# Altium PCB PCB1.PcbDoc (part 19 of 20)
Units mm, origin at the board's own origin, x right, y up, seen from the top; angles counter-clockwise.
Board outline 294.51 x 138.18 mm, 12 copper layers (Top Layer 1 _Signal, L2_GND, L3_Signals, L4_GND, L5_POWER, L6_Signals, L7_GND, L8_Signals, L9_GND, L10_POWER, L11_GND, Bottom Layer_Signals), stack 1.788 mm thick; 1254 components, 836 nets, 5699 pads, 2073 vias.
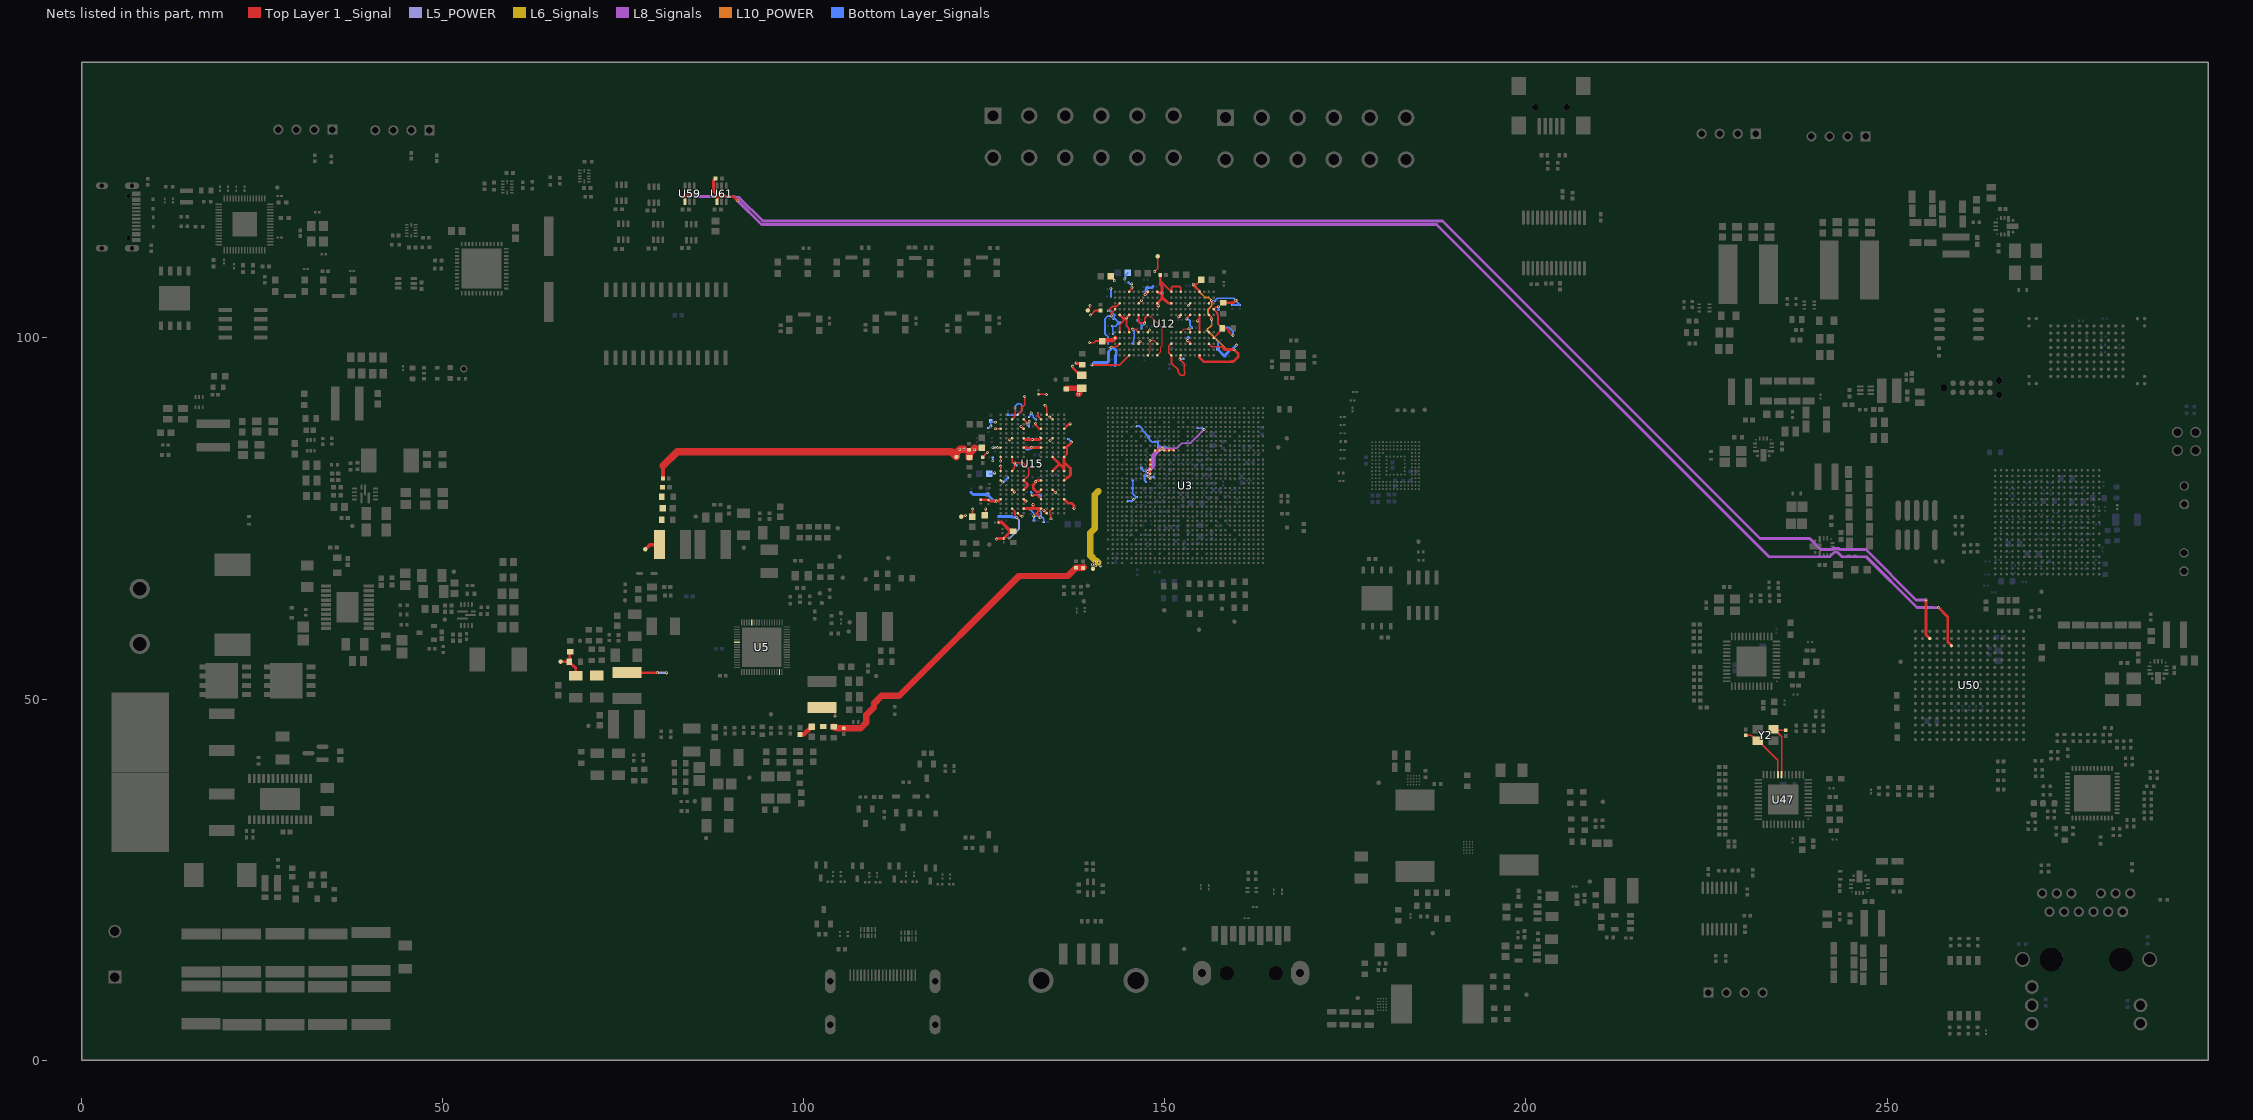
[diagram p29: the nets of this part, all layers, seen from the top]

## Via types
v1: diameter 0.4, hole 0.2, Top Layer 1 _Signal to Bottom Layer_Signals, 2009 vias
v2: diameter 0.508, hole 0.254, Top Layer 1 _Signal to Bottom Layer_Signals, 36 vias
v3: diameter 0.5, hole 0.2, Top Layer 1 _Signal to Bottom Layer_Signals, 12 vias
v4: diameter 1.27, hole 0.711, Top Layer 1 _Signal to Bottom Layer_Signals, 6 vias
v5: diameter 0.3, hole 0.2, Top Layer 1 _Signal to Bottom Layer_Signals, 5 vias
v6: diameter 0.254, hole 0.2, Top Layer 1 _Signal to Bottom Layer_Signals, 3 vias
v7: diameter 0.305, hole 0.2, Top Layer 1 _Signal to Bottom Layer_Signals, 1 vias
v8: diameter 0.254, hole 0.152, Top Layer 1 _Signal to Bottom Layer_Signals, 1 vias

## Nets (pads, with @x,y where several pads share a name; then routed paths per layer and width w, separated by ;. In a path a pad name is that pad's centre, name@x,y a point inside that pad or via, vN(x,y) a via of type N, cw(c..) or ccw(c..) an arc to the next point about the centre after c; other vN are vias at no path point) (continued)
VDDQ_DRAM: C342.1 C344.1 C345.1 C346.1 C356.1 C357.1 C358.1 C359.1 C360.1 C361.1 C362.1 C363.1 C364.1 C365.1 C366.1 C367.1 C368.1 C388.1 C392.1 C416.1 C417.1 C418.1 C419.1 C420.1 C421.1 C422.1 C423.1 C424.1 C425.1 C426.1 C427.1 C428.1 C429.1 C430.1 C431.1 C432.1 C433.1 C551.1 R46.1 R47.1 R51.1 R71.1 R263.1 TP64.1 TP83.1 U12.AA3 U12.AA5 U12.AA8 U12.AA10 U12.B3 U12.B5 U12.B8 U12.B10 U12.D1 U12.D5 U12.D8 U12.D12 U12.F3 U12.F10 U12.U3 U12.U10 U12.W1 U12.W5 U12.W8 U12.W12 U15.AA3 U15.AA5 U15.AA8 U15.AA10 U15.B3 U15.B5 U15.B8 U15.B10 U15.D1 U15.D5 U15.D8 U15.D12 U15.F3 U15.F10 U15.U3 U15.U10 U15.W1 U15.W5 U15.W8 U15.W12 | length 138
  Top Layer 1 _Signal w0.203: v1(126.524,87.421) U15.W12@127.25,87.421 ; v1(128.51,85.886) 128.575,85.886 128.81,86.121 U15.U10@128.85,86.121 ; U15.AA10@128.85,88.721 129.233,89.103 129.233,89.541 129.285,89.593 129.285,89.913 129.27,89.927 129.27,90.262 v1(129.233,90.3) ; v1(130.086,87.735) 130.095,87.735 130.41,87.421 U15.W8@130.45,87.421 ; U15.AA8@130.45,88.721 130.887,88.284 130.887,88.091 v1(130.909,88.07) ; v1(131.842,75.368) 131.947,75.473 131.952,75.473 132.417,75.938 ; R47.1@132.509,92.226 132.509,92.207 132.539,92.177 132.539,92.202 133.561,92.202 v1(133.586,92.177) ; v1(132.734,75.101) 132.734,75.155 132.593,75.296 132.593,75.33 132.417,75.506 132.417,75.938 ; U15.B5@132.85,76.371 132.417,75.938 ; v1(134.237,74.968) 134.175,75.03 134.175,75.406 134.09,75.491 134.09,76.01 U15.B3@134.45,76.371
  Top Layer 1 _Signal w0.254: TP64.1@121.816,75.252 121.882,75.318 122.226,75.318 122.332,75.424 v1(122.372,75.424) ; C431.1@123.351,75.447 v1(123.351,76.305) ; C432.1@125.089,75.443 125.206,75.56 v1(125.206,76.325) ; U15.B10@128.85,76.371 129.264,75.956 129.264,75.902 129.249,75.887 129.249,75.414 129.464,75.198 v1(129.464,75.159) ; v1(134.106,85.802) 134.424,86.121 U15.U3@134.45,86.121 ; U15.F3@134.45,78.971 134.476,78.971 134.805,78.642 134.863,78.642 v1(134.889,78.615) ; v1(139.903,96.271) 143.736,96.271 U12.D1@145.054,97.589 ; v1(142.165,103.768) 142.771,104.375 143.34,104.375 U12.B10@143.754,104.789 ; C367.1@142.524,108.56 142.998,108.087 v1(142.998,107.936) ; v1(142.562,98.681) 142.59,98.709 142.879,98.709 142.945,98.775 143.34,98.775 U12.B3@143.754,99.189 ; U12.B5@143.754,100.789 143.754,101.842 v1(144.679,102.767) 144.679,101.659 145.054,101.283 U12.D5@145.054,100.789 ; U12.D12@145.054,106.389 145.054,106.41 145.437,106.793 v1(145.437,106.973) ; U12.F10@146.354,104.789 146.762,105.196 v1(146.762,105.199) ; v1(148.607,109.187) 148.607,109.213 149.005,109.611 TP83.1@149.005,111.306 ; v1(153.282,104.477) 153.282,104.541 153.504,104.763 U12.U10@153.504,104.789 ; v1(154.535,102.364) 154.535,102.404 154.786,102.655 154.786,102.714 ; U12.W5@154.804,100.789 U12.W8@154.804,103.189 ; U12.W12@154.804,106.389 153.955,107.238 153.955,107.381 v1(153.927,107.409) 153.955,107.436 154.423,107.436 C368.1@155.061,108.074 ; v1(155.829,101.116) 155.829,101.09 156.104,100.814 U12.AA5@156.104,100.789 ; U12.AA3@156.104,99.189 156.506,98.788 157.905,98.788 ; U12.AA8@156.104,103.189 156.104,103.163 156.442,102.825 156.442,102.61 v1(156.483,102.569) v1@156.44,102.525 ; U12.AA10@156.104,104.789 156.104,104.815 156.476,105.186 156.476,105.193 v1(156.484,105.201)
  Top Layer 1 _Signal w0.305: v1(131.623,78.264) 131.641,78.246 132.343,78.246 132.841,77.748 132.841,77.679 U15.D5@132.85,77.671 ; v1(132.104,88.126) 132.122,88.107 132.122,87.916 132.609,87.429 132.841,87.429 U15.W5@132.85,87.421 ; v8(132.448,89.591) 132.448,89.565 132.423,89.541 132.423,89.16 132.85,88.733 U15.AA5@132.85,88.721 ; v1(134.054,89.044) 134.114,89.044 134.438,88.721 U15.AA3@134.45,88.721 ; U15.W1@136.05,87.421 136.72,88.091 v1(136.893,88.091)
  Top Layer 1 _Signal w0.381: C417.1@124.501,77.594 125.542,77.594 C420.1@125.571,77.565 125.687,77.449 125.835,77.449 125.873,77.411 v1(126.707,77.411) 126.991,77.411 U15.D12@127.25,77.671 ; U15.F10@128.85,78.971 128.853,78.971 v1(129.141,78.683) ; U15.B8@130.45,76.371 131.653,76.371 ; U15.D8@130.45,77.671 130.45,77.656 130.71,77.396 v1(130.764,77.396) ; v1(131.623,78.264) 131.623,78.259 v1@131.719,78.163 ; v1(131.748,76.931) 131.745,76.927 131.745,76.462 131.653,76.371 ; U15.B5@132.85,76.371 131.653,76.371 ; U15.D1@136.05,77.671 136.596,77.125 137.065,77.125 137.428,76.762 137.428,76.399 v1(137.431,76.395) ; v1(137.223,96.088) 137.227,96.085 137.227,95.908 138.314,94.82 R263.1@138.491,94.82 ; v1(137.7,96.543) 137.792,96.452 138.381,96.452 C430.1@138.566,96.267 ; U12.B8@143.754,103.189 144.204,102.74 144.646,102.74 144.674,102.767 v1(144.679,102.767) 144.679,102.772 145.054,103.148 U12.D8@145.054,103.189 ; U12.F3@146.354,99.189 146.354,99.259 146.562,99.466 v1(146.562,99.472) ; v1(153.157,99.644) 153.157,99.639 153.504,99.292 U12.U3@153.504,99.189 ; U12.W1@154.804,97.589 154.804,97.284 155.377,96.711 159.213,96.711 159.238,96.736 159.518,96.736 160.146,97.364 160.146,97.836 v1(159.573,98.41) 158.283,98.41 157.905,98.788 ; C366.1@158.106,104.874 159.49,104.874 v1(159.837,105.221)
  L5_POWER w0.254: v1(128.421,72.312) 128.449,72.34 128.601,72.34 129.824,73.563 129.824,74.76 129.464,75.119 v1(129.464,75.159)
  L10_POWER w0.254: v1(153.927,107.409) 154.775,106.56 154.775,106.421 155.595,105.601 156.062,105.601 156.461,105.201 v1(156.484,105.201) 156.484,104.482 155.982,103.979 155.982,103.323 156.483,102.822 v1(156.483,102.569) 156.483,101.77 v1(155.829,101.116) 158.535,98.41 v1(159.573,98.41)
  Bottom Layer_Signals w0.089: v1(130.909,88.07) 130.968,88.01 130.968,87.921 131.024,87.865 131.122,87.865 131.218,87.77 C425.1@131.218,87.76 ; v1(156.484,105.201) 156.819,105.201 C357.1@156.915,105.106
  Bottom Layer_Signals w0.203: C429.1@125.549,87.525 125.587,87.563 125.597,87.563 125.758,87.724 125.797,87.724 125.865,87.793 v1(125.918,87.793) 125.902,87.81 125.902,88.465 C433.1@125.9,88.466 ; C433.1@125.885,88.482 C433.1@125.9,88.466 ; v1(126.531,88.321) 126.493,88.359 126.008,88.359 C433.1@125.9,88.466 ; R46.1@128.259,89.337 128.271,89.326 129.54,89.326 C427.1@129.546,89.319 129.556,89.319 129.761,89.524 129.773,89.524 130.168,89.919 130.168,90.296 130.186,90.314 130.186,90.691 129.96,90.916 129.641,90.916 129.27,90.546 129.27,90.338 v1(129.233,90.3) ; C425.1@131.199,87.76 C425.1@131.218,87.76 ; C425.1@131.203,87.783 131.203,88.398 v1(131.227,88.422) ; C428.1@131.213,89.055 131.213,89.065 131.323,89.175 131.38,89.175 131.38,89.436 v1@131.493,89.548 ; C426.1@131.435,76.159 131.473,76.12 131.483,76.12 131.65,75.954 131.662,75.954 131.865,75.75 v1@131.865,75.493 ; v1(131.493,89.602) v1@131.493,89.548 ; v1(131.842,75.368) v1@131.842,75.421 ; v1@131.865,75.315 131.88,75.33 132.297,75.33 132.312,75.315 132.765,75.315 132.874,75.424 132.874,75.857 132.743,75.988 132.731,75.988 132.587,76.132 132.577,76.132 C423.1@132.539,76.171 ; C422.1@132.138,88.693 132.128,88.693 131.946,88.875 131.934,88.875 131.803,89.006 131.803,89.238 v1@131.493,89.548 ; v1(132.734,75.101) 132.666,75.169 132.666,75.23 132.97,75.23 133.229,74.97 133.229,74.548 R51.1@133.243,74.534 ; v1(142.165,103.768) 142.202,103.73 142.473,103.73 142.98,103.223 142.98,102.779 142.977,102.779 142.86,102.663 C365.1@142.86,102.653 142.884,102.629 143.124,102.629 143.266,102.486 143.266,102.456 143.3,102.456 143.3,102.43 C392.1@143.681,102.049 143.523,101.891 143.416,101.891 143.177,101.651 142.736,101.651 142.686,101.651 C359.1@142.683,101.654 142.721,101.616 142.721,101.524 142.759,101.487 142.759,100.736 142.787,100.708 142.787,100.606 C344.1@142.825,100.568
  Bottom Layer_Signals w0.254: v1@131.87,75.34 131.861,75.331 131.861,74.739 131.866,74.734 R71.1@131.881,74.734 ; C364.1@142.547,105.755 142.559,105.768 142.559,106.722 C362.1@142.572,106.734 ; C363.1@144.979,107.678 144.992,107.665 144.992,107.631 145.147,107.475 v1(145.411,107.475) ; C357.1@156.915,105.102 156.928,105.115 156.928,105.125 157.043,105.241 157.043,105.289 157.258,105.503 159.515,105.503 159.865,105.154 159.865,105.098 C358.1@160.379,104.584 ; C342.1@157.241,99.7 157.241,99.69 157.341,99.59 C388.1@157.341,98.504 ; C345.1@159.341,104.562 160.358,104.562 C358.1@160.379,104.584 ; C358.1@160.389,104.584 C358.1@160.379,104.584
  Bottom Layer_Signals w0.305: C418.1@131.471,78.643 131.605,78.509 131.605,78.283 v1(131.623,78.264) 132.59,78.264 C416.1@132.781,78.074
  Bottom Layer_Signals w0.381: C424.1@123.168,78.618 123.468,78.318 C551.1@125.423,78.318 126.327,77.415 126.703,77.415 v1(126.707,77.411) ; C419.1@126.966,75.29 126.969,75.287 127.97,75.287 127.984,75.273 C421.1@127.991,75.273 128.007,75.29 128.784,75.29 128.911,75.162 129.461,75.162 v1(129.464,75.159) ; v1(139.903,96.271) 139.903,96.276 140.209,96.582 142.018,96.582 142.209,96.773 142.209,98.099 142.558,98.449 142.558,98.678 v1(142.562,98.681) ; v1@142.562,98.691 v1(142.562,98.681) ; C346.1@143.102,96.306 C346.1@143.102,96.158 143.153,96.209 C356.1@143.153,97.036 143.153,97.565 143.279,97.692 143.279,98.221 142.823,98.678 142.566,98.678 v1(142.562,98.681) ; v1(153.157,99.644) 153.161,99.648 153.161,99.981 C361.1@153.254,100.074 ; C388.1@157.341,98.504 157.411,98.434 157.411,98.326 158.23,97.507 C360.1@158.356,97.507 ; C360.1@158.333,97.531 158.356,97.554 158.356,97.655 159.108,98.406 159.569,98.406 v1(159.573,98.41) ; v1@159.445,98.538 v1(159.901,98.994)
  other v1: 142.536,106.849
VOUT6: C55.1 C56.1 C57.1 C58.1 C325.1 C327.1 C328.1 C331.1 C332.1 C333.1 C334.1 C335.1 C336.1 C337.1 C338.1 C339.1 C340.1 C341.1 C402.1 C403.1 C404.1 C405.1 C406.1 C407.1 C408.1 C409.1 C410.1 C411.1 C412.1 C413.1 C414.1 C415.1 L3.2 R32.2 R44.1 R45.1 R48.1 R49.1 R264.2 TP14.1 TP63.1 TP82.1 U5.30 U12.A4 U12.A9 U12.AB4 U12.AB9 U12.F5 U12.F8 U12.H1 U12.H5 U12.H8 U12.H12 U12.K1 U12.K3 U12.K10 U12.K12 U12.N1 U12.N3 U12.N10 U12.N12 U12.R1 U12.R5 U12.R8 U12.R12 U12.U5 U12.U8 U15.A4 U15.A9 U15.AB4 U15.AB9 U15.F5 U15.F8 U15.H1 U15.H5 U15.H8 U15.H12 U15.K1 U15.K3 U15.K10 U15.K12 U15.N1 U15.N3 U15.N10 U15.N12 U15.R1 U15.R5 U15.R8 U15.R12 U15.U5 U15.U8 | length 170.1
  Top Layer 1 _Signal w0.127: U12.H1@147.654,97.589 147.935,97.869 147.935,98.213 147.977,98.255 147.977,99.322 147.953,99.346 147.953,99.607 v1(147.935,99.626)
  Top Layer 1 _Signal w0.152: U12.H5@147.654,100.789 147.654,100.842 147.854,101.042 v1(147.854,101.099) ; U12.H8@147.654,103.163 147.734,103.163 147.95,102.947 148.073,102.947 148.166,102.854 148.215,102.854 148.307,102.762 148.307,102.677 148.729,102.255 148.807,102.255 149.627,101.435 149.627,98.91 149.463,98.746 149.463,98.097 U12.K1@148.954,97.589 ; v1(147.935,99.626) 147.958,99.649 148.494,99.649 U12.K3@148.954,99.189 ; U12.R5@152.204,100.789 152.689,101.273 v1(153.343,101.273)
  Top Layer 1 _Signal w0.203: v1(126.836,84.821) U15.R12@127.25,84.821 ; v1(127.221,82.956) 127.25,82.985 U15.N12@127.25,83.521 ; U15.H12@127.25,80.271 127.278,80.271 127.519,80.03 v1(127.547,80.03) ; U15.K12@127.25,81.571 v1(127.25,82.243) ; U15.K10@128.85,81.571 128.85,81.61 128.923,81.684 128.923,81.748 129.115,81.94 129.115,82.551 129.173,82.609 129.173,82.645 v1@129.12,82.698 ; 128.85,82.659 128.85,82.698 ; U15.N10@128.85,83.521 128.85,82.698 ; v1@129.211,82.698 130.321,82.698 131.163,81.856 131.163,80.984 U15.H8@130.45,80.271 ; v1(129.211,82.7) 129.209,82.698 v1@129.12,82.698 ; U12.N1@150.904,97.589 150.544,97.949 150.544,98.828 U12.N3@150.904,99.189 ; 151.836,95.573 151.836,95.221 152.197,94.861 152.589,94.861 152.742,95.014 152.742,95.406 152.708,95.44 152.708,96.432 v1(152.08,97.06) ; 128.85,82.698 v1@129.12,82.698
  Top Layer 1 _Signal w0.25: U15.A9@129.65,75.721 130.058,75.313 v1(130.239,75.313) ; U12.N1@150.904,97.589 150.904,96.505 151.836,95.573
  Top Layer 1 _Signal w0.254: C415.1@124.772,83.479 125.434,84.141 v1(125.434,84.146) ; U15.AB9@129.65,89.371 130.143,89.863 130.143,90.292 130.592,90.742 130.592,91.893 v1(130.59,91.895) ; v1(133.41,90.683) 133.41,90.644 133.65,90.404 U15.AB4@133.65,89.371 ; U15.N1@136.05,83.521 136.05,83.535 136.436,83.921 136.436,84.704 136.319,84.821 ; TP82.1@139.333,103.814 139.333,103.908 139.619,104.194 139.619,104.436 v1(139.647,104.464) ; v1@139.645,99.337 140.187,99.337 140.41,99.56 C340.1@141.306,99.56 ; v1(139.708,103.159) 140.359,103.811 C341.1@141.074,103.811 ; v1(142.595,103.063) 142.623,103.091 142.623,103.507 U12.A9@143.104,103.989 ; v1(145.544,101.219) 145.558,101.204 145.939,101.204 U12.F5@146.354,100.789 U12.F5@146.369,100.789 ; U12.F8@146.354,103.189 146.336,103.171 146.336,102.96 146.332,102.957 146.332,102.528 146.354,102.506 146.354,102.245 146.548,102.051 v1(147.212,102.051) 147.212,102.721 147.654,103.163 U12.H8@147.654,103.189 ; 149.375,107.919 U12.N12@150.904,106.389 150.904,106.977 151.053,107.125 152.056,107.125 152.204,106.977 U12.R12@152.204,106.389 ; v1(153.026,102.644) 153.026,102.71 U12.U8@153.504,103.189 ; v1(153.343,101.273) 153.486,101.131 153.486,100.807 U12.U5@153.504,100.789 ; U12.AB4@156.754,99.989 157.693,100.927 157.693,101.058 C338.1@157.941,101.306 ; v1(157.405,104.322) 157.377,104.294 157.085,104.294 156.78,103.989 U12.AB9@156.754,103.989 157.233,103.51 157.233,103.278 157.359,103.152 157.359,102.207 157.343,102.19 157.343,101.98 157.941,101.381 C338.1@157.941,101.306 ; v1(159.461,100.356) 159.318,100.356 158.837,100.837 158.837,101.115 158.645,101.306 C338.1@157.941,101.306
  Top Layer 1 _Signal w0.381: v1(126.708,72.138) 126.796,72.226 R48.1@127.687,72.226 127.947,72.486 127.947,72.509 128.481,73.043 128.81,73.043 C412.1@128.994,73.228 ; U15.F8@130.45,78.971 130.899,79.42 130.899,79.821 U15.H8@130.45,80.271 ; U15.R8@130.45,84.821 130.767,84.821 130.778,84.809 131.545,84.809 v1(131.549,84.806) 131.553,84.809 132.32,84.809 132.331,84.821 U15.R5@132.85,84.821 ; U15.U8@130.45,86.121 130.638,85.932 v1(131.649,85.932) 132.662,85.932 U15.U5@132.85,86.121 ; 132.279,80.271 v1(132.123,80.115) 132.123,80.109 131.997,79.983 131.997,79.827 131.782,79.612 131.782,79.126 132.235,78.673 132.552,78.673 U15.F5@132.85,78.971 ; 132.324,80.271 U15.H5@132.85,80.271 ; v1(133.259,76.13) 133.259,76.112 U15.A4@133.65,75.721 ; U15.K3@134.45,81.571 135.425,82.546 ; U15.N3@134.45,83.521 135.425,82.546 ; U15.H1@136.05,80.271 136.405,80.626 136.532,80.626 136.94,81.034 136.94,81.938 136.05,82.828 U15.N1@136.05,83.521 ; U15.K1@136.05,81.571 136.05,81.921 ; 136.05,82.753 136.05,81.921 ; U15.R1@136.05,84.821 136.319,84.821 136.608,85.11 136.668,85.11 136.946,85.387 136.946,85.442 137.068,85.565 v1(137.068,85.57) ; v1@147.265,106.014 v1(147.269,106.014) 147.269,106.018 147.64,106.389 U12.H12@147.654,106.389 ; U12.K10@148.954,104.789 U12.K10@149.06,104.894 ; U12.K12@148.954,106.389 149.118,106.226 149.613,106.226 v1(149.617,106.222) 149.616,107.167 149.375,107.408 149.375,107.919 C325.1@149.375,108.727 ; v1(149.096,104.425) 149.06,104.462 U12.K10@149.06,104.894 ; 149.616,105.451 U12.K10@149.06,104.894 ; v1(149.617,106.222) 149.617,105.631 150.118,105.13 150.19,105.13 150.531,104.789 U12.N10@150.904,104.789 ; v1@151.939,102.879 v1@151.939,102.886 ; v1(151.94,102.93) 151.945,102.93 U12.R8@152.204,103.189 ; v1@152.141,97.238 152.141,97.526 U12.R1@152.204,97.589 ; 135.425,82.546 136.05,81.921
  Top Layer 1 _Signal w0.508: TP14.1@78.061,70.738 78.693,71.37 L3.2@80.031,71.37 ; C55.1@80.515,80.539 80.515,82.301 ; C410.1@126.976,74.464 127.41,74.464 128.526,73.349 128.873,73.349 C412.1@128.994,73.228
  Top Layer 1 _Signal w0.635: C340.1@141.306,99.56 141.439,99.693 142.808,99.693 U12.A4@143.104,99.989
  Top Layer 1 _Signal w1.016: 80.515,82.301 82.458,84.244 120.415,84.244 TP63.1@121.136,83.522 121.136,84.102 121.636,84.602 v1(122.184,84.602) ; R264.2@122.897,83.468 122.897,83.889 ; R264.2@122.927,83.438 122.927,84.012 123.12,84.205 123.162,84.247 123.675,84.761
  Bottom Layer_Signals w0.152: v1(152.08,97.06) 152.539,97.06 152.588,97.109 R45.1@152.588,97.139
  Bottom Layer_Signals w0.203: C413.1@125.67,81.195 126.321,81.195 v1(126.445,81.32) ; v1(126.169,82.99) C403.1@126.169,83.442 ; v1(126.18,84.797) C404.1@126.489,84.797 ; v1(127.547,80.03) 127.684,80.03 128.061,80.407 128.061,80.419 128.266,80.624 C408.1@128.266,80.634 ; v1(129.211,82.7) 129.249,82.662 129.249,82.549 129.424,82.374 C411.1@129.424,82.364 ; v1(145.544,101.219) 145.779,100.984 145.779,99.855 145.682,99.759 145.682,99.44 145.63,99.387 145.63,99.235 145.607,99.212 R44.1@145.583,99.212
  Bottom Layer_Signals w0.25: v1(157.405,104.322) 157.407,104.32 C333.1@157.407,103.885
  Bottom Layer_Signals w0.254: v1(131.649,85.932) 131.689,85.932 131.795,85.827 132.416,85.827 132.603,86.014 132.603,86.062 132.719,86.177 C407.1@132.719,86.187 ; R49.1@136.634,85.993 136.68,85.993 137.068,85.605 v1(137.068,85.57) ; C334.1@142.128,99.235 142.128,100.134 141.723,100.539 141.723,102.652 142.107,103.035 142.567,103.035 v1(142.595,103.063) ; v1(144.445,108.161) 144.561,108.277 144.561,108.527 144.565,108.531 144.565,108.704 C339.1@144.888,109.027 ; C328.1@146.227,102.443 146.227,102.433 146.407,102.254 146.407,102.206 146.734,101.878 146.734,101.514 ; C327.1@146.734,101.324 146.744,101.334 146.744,101.514 147.212,101.982 v1(147.212,102.051) ; v1(153.026,102.644) 153.054,102.616 153.211,102.616 153.467,102.36 153.467,101.749 153.753,101.463 153.753,101.42 C335.1@153.766,101.407 ; C331.1@158.137,101.052 158.137,101.062 158.266,101.19 158.266,101.239 158.48,101.453 158.854,101.453 159.433,100.873 159.433,100.384 v1(159.461,100.356)
  Bottom Layer_Signals w0.381: C406.1@130.886,84.617 131.19,84.617 131.292,84.72 131.458,84.72 131.544,84.806 132.644,84.806 C409.1@132.664,84.826 ; C405.1@131.051,86.05 131.124,86.05 C405.1@131.146,86.05 ; C405.1@131.146,86.073 131.283,85.936 131.646,85.936 v1(131.649,85.932) ; v1(147.269,106.014) 147.269,106.019 147.384,106.134 147.384,106.719 147.463,106.799 C337.1@147.463,106.947 ; C337.1@147.579,107.062 C337.1@147.463,106.947 ; C336.1@148.373,107.138 148.182,106.947 C337.1@147.463,106.947
  other v1: 123.62,84.522 121.598,84.569 139.558,99.377
VOUT7: C180.1 C181.1 L13.2 R292.1 R293.1 TP36.1 U5.41 | length 10.5
  Top Layer 1 _Signal w0.381: TP36.1@66.33,55.179 66.332,55.177 67.537,55.177 C180.1@67.539,55.175 ; C181.1@67.639,56.534 67.589,56.484 67.589,55.225 C180.1@67.539,55.175 ; R293.1@68.423,53.232 68.423,54.29 68.154,54.56 68.079,54.56 67.539,55.1 C180.1@67.539,55.175 ; L13.2@75.506,53.65 v1(79.72,53.65)
  L5_POWER w0.381: v1(79.72,53.65) 80.987,53.65 v1(81.013,53.624)
VOUT9: C69.1 C70.1 C71.1 C72.1 C283.2 C284.2 C285.2 C286.1 C287.1 C288.1 C289.2 C290.2 C291.2 C292.1 C293.1 C294.1 L7.2 R35.2 R70.1 R263.2 R265.2 R274.1 R275.2 R303.2 TP55.1 U3.K11 U3.K12 U3.K13 U3.K14 U3.K15 U3.M10 U3.N10 U3.P10 U3.R10 U3.T10 U5.67 | length 95.4
  Top Layer 1 _Signal w0.203: L7.2@102.538,48.841 103.678,48.841 104.327,48.192 v1(104.327,47.659)
  Top Layer 1 _Signal w0.254: v1(147.686,80.854) 147.686,80.838 147.979,80.544 U3.T10@147.979,80.528 147.697,80.81 147.697,80.896 U3.R10@147.979,81.178 U3.P10@147.979,81.828 U3.N10@147.979,82.478 U3.M10@147.979,83.138 ; U3.K11@148.629,84.428 U3.K12@149.279,84.428 149.287,84.428 149.583,84.724 v1(149.591,84.724) 149.615,84.724 149.911,84.428 U3.K13@149.929,84.428 U3.K14@150.579,84.428 150.597,84.428 150.65,84.481 151.065,84.481 151.106,84.441 151.217,84.441 U3.K15@151.229,84.428
  Top Layer 1 _Signal w0.635: R35.2@99.502,45.087 99.502,45.112 99.534,45.144 100.037,45.144 100.496,45.603 100.563,45.603 C72.1@101.112,46.152
  Top Layer 1 _Signal w0.762: R265.2@136.337,92.937 136.337,92.963 136.39,93.016 R263.2@138.491,93.016 R263.2@138.463,93.016 ; v1(138.017,92.197) 138.191,92.372 138.191,92.893 R263.2@138.314,93.016
  Top Layer 1 _Signal w0.889: C70.1@104.121,46.188 104.306,46.004 104.652,46.004 104.692,45.964 C69.1@105.524,45.964 107.878,45.964 108.68,46.765 108.68,47.825 109.724,48.87 109.724,49.391 110.769,50.436 113.213,50.436 129.81,67.033 136.564,67.033 C283.2@137.7,68.169 C289.2@138.677,68.169 ; C289.2@138.677,68.147 C289.2@138.799,68.269
  L6_Signals w0.889: v1(140.777,68.954) 140.644,69.087 140.47,69.087 139.695,69.862 139.695,73.018 140.289,73.612 140.289,78.271 140.81,78.792
  L8_Signals w0.254: v1(149.591,84.724) 151.649,84.724 152.348,85.423 153.502,85.423 v1(155.432,87.353)
  L8_Signals w0.635: v1(147.632,81.503) 148.414,82.285 148.414,83.711 148.653,83.95 148.653,84.026 149.321,84.694 149.561,84.694 v1(149.591,84.724)
  Bottom Layer_Signals w0.254: C284.2@144.933,77.41 144.946,77.423 145.462,77.423 145.642,77.603 v1(145.682,77.603) R70.1@146.029,77.949 ; C292.1@145.558,80.265 145.554,80.261 145.554,79.201 145.546,79.194 145.546,78.432 R70.1@146.029,77.949 ; R70.1@146.074,77.949 R70.1@146.029,77.949 ; R303.2@146.214,87.82 146.218,87.816 146.472,87.816 146.896,87.392 146.896,87.238 147.728,86.407 147.728,86.19 147.732,86.186 147.823,86.186 147.828,86.181 147.828,85.973 148.194,85.606 C294.1@148.986,85.606 148.986,85.56 149.046,85.501 149.046,85.017 149.05,85.013 C293.1@149.05,84.97 ; C287.1@146.726,82.05 146.771,82.05 146.91,81.911 146.91,81.821 ; 146.911,81.821 146.911,81.68 147.059,81.531 147.604,81.531 v1(147.632,81.503) ; C285.2@147.38,80.065 147.38,80.075 147.237,80.218 147.237,80.293 147.198,80.293 C291.2@147.198,80.968 147.198,80.958 147.211,80.945 147.556,80.945 147.646,80.854 v1@147.725,80.854 ; v1(147.686,80.854) v1@147.725,80.854 ; C288.1@148.466,80.741 147.839,80.741 v1@147.725,80.854 ; C293.1@149.05,84.967 C293.1@149.05,84.97 ; C286.1@150.157,84.822 150.153,84.817 149.724,84.817 149.631,84.724 v1(149.591,84.724) 149.345,84.97 C293.1@149.05,84.97 ; R275.2@154.548,87.49 155.255,87.49 155.392,87.353 v1(155.432,87.353) v1@155.432,87.33
  other v1: 141.11,68.431 140.428,68.484 139.98,68.596 140.302,68.95
VSC_COMA: R285.1 U50.L3 U61.4 | length 202.8
  Top Layer 1 _Signal w0.381: R285.1@87.76,122.077 87.49,121.806 87.49,120.303 87.766,120.027 87.766,119.924 87.964,119.726 87.964,119.383 U61.4@87.964,118.849 ; 88.14,119.383 88.329,119.573 90.281,119.573 v1(90.86,118.994) ; v1(257.131,62.658) 258.411,61.378 258.411,57.902 258.919,57.394 U50.L3@258.919,57.379
  L8_Signals w0.381: v1(90.86,118.994) 94.133,115.721 187.634,115.721 233.655,69.7 242.044,69.7 242.715,70.371 243.108,70.371 243.778,69.7 247.128,69.7 254.153,62.675 256.508,62.675 256.528,62.655 257.127,62.655 v1(257.131,62.658)
VSC_MDC: U50.P2 U59.4 | length 201.5
  Top Layer 1 _Signal w0.381: U59.4@83.535,118.879 83.535,119.49 83.807,119.762 84.646,119.762 v1(84.663,119.78) ; v1(255.412,63.723) v1(255.412,63.723) 255.411,58.902 255.919,58.394 U50.P2@255.919,58.379
  L8_Signals w0.381: v1(84.663,119.78) 84.668,119.78 84.864,119.583 90.416,119.583 90.53,119.469 91.056,119.469 94.336,116.189 188.429,116.189 232.408,72.21 239.295,72.21 240.815,70.691 242.377,70.691 242.522,70.836 243.3,70.836 243.445,70.691 247.068,70.691 254.035,63.723 v1(255.412,63.723)
XI: C598.1 U47.20 Y2.1 | length 7.9
  Top Layer 1 _Signal w0.203: C598.1@230.438,44.992 231.203,44.992 231.994,44.201 232.194,44.201 234.881,41.514 234.881,39.542 U47.20@234.887,39.535
XO: C599.1 U47.19 Y2.3 | length 8.5
  Top Layer 1 _Signal w0.203: U47.19@235.388,39.535 235.388,44.808 234.394,45.801 Y2.3@234.294,45.801 234.419,45.676 C599.1@235.984,45.676
pads on no net: C3.2 C4.2 IC1.4 IC1.5 IC1.7 IC1.8 IC2.3 IC2.4 IC2.5 IC2.7 IC2.9 IC.2 IC.3 IC.5 IC.7 IC.9 IC.10 J1.A J1.B J1.C J7.MH1 J7.MH2 J10.9 J10.10 J10.11 J10.12 J333. J333.15 P3.4 R400.2 U1.A6 U1.A8 U1.A10 U1.A12 U1.A14 U1.A17 U1.A18 U1.B6 U1.B7 U1.B8 U1.B9 U1.B10 U1.B11 U1.B12 U1.B13 U1.B14 U1.B17 U1.B18 U1.B19 U1.C7 U1.C9 U1.C11 U1.C13 U1.C17 U1.C18 U1.C19 U1.D6 U1.D8 U1.D10 U1.D12 U1.D14 U1.D17 U1.D18 U1.D19 U1.E6 U1.E7 U1.E8 U1.E9 U1.E10 U1.E11 U1.E12 U1.E13 U1.E14 U1.E17 U1.E18 U1.F7 U1.F9 U1.F11 U1.F13 U1.J3 U1.K2 U1.K3 U1.K18 U1.K19 U1.L1 U1.L2 U1.L3 U1.L17 U1.L18 U1.M1 U1.M2 U1.N2 U1.R7 U1.R9 U1.R11 U1.R13 U1.T1 U1.T2 U1.T3 U1.T4 U1.T5 U1.T6 U1.T7 U1.T8 U1.T9 U1.T10 U1.T11 U1.T12 U1.T13 U1.T14 U1.T15 U1.U1 U1.U2 U1.U3 U1.U4 U1.U5 U1.U6 U1.U7 U1.U8 U1.U9 U1.U10 U1.U11 U1.U12 U1.U13 U1.U14 U1.U15 U1.V1 U1.V2 U1.V3 U1.V4 U1.V5 U1.V6 U1.V7 U1.V8 U1.V9 U1.V10 U1.V11 U1.V12 U1.V13 U1.V14 U1.V15 U1.W2 U1.W3 U1.W4 U1.W5 U1.W6 U1.W7 U1.W8 U1.W9 U1.W10 U1.W11 U1.W12 U1.W13 U1.W14 U1.W15 U1.W16 U3.A24 U3.A25 U3.A26 U3.A28 U3.A30 U3.A32 U3.A33 U3.AA25 U3.AA26 U3.AA27 U3.AB25 U3.AB26 U3.AB28 U3.AB30 U3.AC9 U3.AC30 U3.AD1 U3.AD2 U3.AD4 U3.AD6 U3.AD7 U3.AD9 U3.AD30 U3.AE1 U3.AE2 U3.AE28 U3.AE30 U3.AF1 U3.AF2 U3.AF18 U3.AF19 U3.AF20 U3.AF33 U3.AG9 U3.AG13 U3.AG16 U3.AG19 U3.AG20 U3.AG24 U3.AG25 U3.AG31 U3.AG32 U3.AG33 U3.AG34 U3.AH9 U3.AH13 U3.AH19 U3.AH20 U3.AH27 U3.AH31 U3.AH32 U3.AH33 U3.AH34 U3.AJ13 U3.AJ19 U3.AJ20 U3.AJ27 U3.AJ31 U3.AJ32 U3.AJ33 U3.AJ34 U3.AK6 U3.AK8 U3.AK15 U3.AK16 U3.AK17 U3.AK18 U3.AK19 U3.AK20 U3.AK21 U3.AK22 U3.AK31 U3.AK32 U3.AK33 U3.AK34 U3.AL6 U3.AL7 U3.AL8 U3.AL10 U3.AL14 U3.AL17 U3.AL18 U3.AL19 U3.AL20 U3.AL21 U3.AL22 U3.AL24 U3.AL28 U3.AL29 U3.AL31 U3.AL32 U3.AL33 U3.AL34 U3.AM3 U3.AM5 U3.AM7 U3.AM10 U3.AM17 U3.AM25 U3.AM27 U3.AM31 U3.AM32 U3.AM33 U3.AM34 U3.AN1 U3.AN2 U3.AN3 U3.AN4 U3.AN5 U3.AN6 U3.AN8 U3.AN9 U3.AN10 U3.AN11 U3.AN17 U3.AN18 U3.AN19 U3.AN20 U3.AN21 U3.AN22 U3.AN24 U3.AN25 U3.AN26 U3.AN27 U3.AN28 U3.AN29 U3.AN30 U3.AN32 U3.AN33 U3.AN34 U3.AP2 U3.AP4 U3.AP6 U3.AP8 U3.AP9 U3.AP10 U3.AP11 U3.AP18 U3.AP19 U3.AP20 U3.AP21 U3.AP22 U3.AP24 U3.AP25 U3.AP26 U3.AP27 U3.AP28 U3.AP29 U3.AP30 U3.AP31 U3.AP32 U3.AP33 U3.B28 U3.B29 U3.B30 U3.B31 U3.B32 U3.B34 U3.C19 U3.C29 U3.C31 U3.C33 U3.C34 U3.D7 U3.D10 U3.D14 U3.D17 U3.D28 U3.D29 U3.D30 U3.D32 U3.D33 U3.E7 U3.E10 U3.E17 U3.E25 U3.E26 U3.E28 U3.E29 U3.E30 U3.E31 U3.E33 U3.E34 U3.F26 U3.F27 U3.F28 U3.F30 U3.F32 U3.F33 U3.G9 U3.G18 U3.G20 U3.G23 U3.G24 U3.G26 U3.G27 U3.G29 U3.G30 U3.G31 U3.G33 U3.G34 U3.H4 U3.H5 U3.H9 U3.H18 U3.H23 U3.H24 U3.H29 U3.H30 U3.H32 U3.H33 U3.J30 U3.J31 U3.J33 U3.J34 U3.K4 U3.K5 U3.K7 U3.K27 U3.K28 U3.K29 U3.K33 U3.K34 U3.L27 U3.L28 U3.L30 U3.L32 U3.L33 U3.M7 U3.M27 U3.M28 U3.M33 U3.M34 U3.N33 U3.N34 U3.P30 U3.P33 U3.R30 U3.T28 U3.T29 U3.T31 U3.V6 U3.V7 U3.W4 U3.W5 U4.A1 U4.A2 U4.A9 U4.A10 U4.B1 U4.B10 U4.D2 U4.D3 U4.D4 U4.D5 U4.D6 U4.D7 U4.D8 U4.D9 U4.E2 U4.E3 U4.E5 U4.E6 U4.E7 U4.E8 U4.E9 U4.H4 U4.H5 U4.H6 U4.H7 U4.J2 U4.J3 U4.J4 U4.J6 U4.J7 U4.J8 U4.J9 U4.K4 U4.K5 U4.K6 U4.K7 U4.L5 U4.L6 U4.M2 U4.M3 U4.M6 U4.M8 U4.M9 U4.N4 U4.N5 U4.N6 U4.N7 U4.P4 U4.P7 U4.T1 U4.T10 U4.U1 U4.U2 U4.U9 U4.U10 U5.2 U5.3 U5.16 U5.31 U5.38 U5.47 U5.48 U6.1 U6.2 U6.3 U6.7 U7.9 U8.2 U8.3 U8.6 U8.8 U8.9 U8.10 U8.11 U8.12 U8.13 U8.14 U8.19 U8.22 U8.23 U8.24 U8.26 U8.27 U8.28 U10.A1 U10.A2 U10.A7 U10.A8 U10.A9 U10.A10 U10.A11 U10.A12 U10.A13 U10.A14 U10.B1 U10.B7 U10.B8 U10.B9 U10.B10 U10.B11 U10.B12 U10.B13 U10.B14 U10.C1 U10.C3 U10.C5 U10.C7 U10.C8 U10.C9 U10.C10 U10.C11 U10.C12 U10.C13 U10.C14 U10.D1 U10.D2 U10.D3 U10.D4 U10.D12 U10.D13 U10.D14 U10.E1 U10.E2 U10.E3 U10.E5 U10.E7 U10.E8 U10.E9 U10.E10 U10.E12 U10.E13 U10.E14 U10.F1 U10.F2 U10.F3 U10.F10 U10.F12 U10.F13 U10.F14 U10.G1 U10.G2 U10.G3 U10.G5 U10.G10 U10.G12 U10.G13 U10.G14 U10.H1 U10.H2 U10.H3 U10.H12 U10.H13 U10.H14 U10.J1 U10.J2 U10.J3 U10.J12 U10.J13 U10.J14 U10.K1 U10.K2 U10.K3 U10.K6 U10.K7 U10.K10 U10.K12 U10.K13 U10.K14 U10.L1 U10.L2 U10.L3 U10.L12 U10.L13 U10.L14 U10.M1 U10.M2 U10.M3 U10.M7 U10.M8 U10.M9 U10.M10 U10.M11 U10.M12 U10.M13 U10.M14 U10.N1 U10.N3 U10.N6 U10.N7 U10.N8 U10.N9 U10.N10 U10.N11 U10.N12 U10.N13 U10.N14 U10.P1 U10.P2 U10.P6 U10.P7 U10.P8 U10.P9 U10.P10 U10.P11 U10.P12 U10.P13 U10.P14 U12.A1 U12.A2 U12.A11 U12.A12 U12.AA1 U12.AA12 U12.AB1 U12.AB2 U12.AB11 U12.AB12 U12.B1 U12.B12 U12.G11 U12.K5 U12.K8 U12.N5 U12.N8 U12.T11 U15.A1 U15.A2 U15.A11 U15.A12 U15.AA1 U15.AA12 U15.AB1 U15.AB2 U15.AB11 U15.AB12 U15.B1 U15.B12 U15.G11 U15.K5 U15.K8 U15.N5 U15.N8 U18.4 U19.4 U22.A2 U32.7 U32.8 U32.9 U32.10 U35.4 U35.5 U35.7 U35.8 U35.18 U35.19 U35.24 U35.25 U35.27 U35.28 U35.29 U35.31 U35.40 U35.41 U35.42 U35.43 U42.6 U42.14 U42.23 U42.25 U42.27 U43.1 U43.2 U43.3 U43.4 U43.5 U43.6 U43.7 U43.8 U43.11 U43.14 U43.19 U43.20 U43.22 U44.7 U44.11 U44.12 U44.13 U44.14 U44.15 U44.16 U44.19 U44.20 U44.21 U44.22 U44.23 U44.24 U44.25 U44.26 U44.27 U44.28 U44.29 U44.30 U44.31 U44.32 U44.33 U44.34 U44.35 U44.36 U44.37 U44.38 U44.39 U44.40 U44.41 U44.42 U44.43 U45.44 U45.45 U47.1 U47.2 U47.4 U47.5 U47.7 U47.8 U47.10 U47.11 U47.40 U47.44 U47.45 U47.46 U47.47 U49.1 U49.2 U49.4 U49.5 U49.7 U49.8 U49.10 U49.11 U49.40 U49.44 U49.45 U49.46 U49.47 U50.A1 U50.A2 U50.A3 U50.A4 U50.A5 U50.A6 U50.A7 U50.A8 U50.A9 U50.A10 U50.A11 U50.A12 U50.A13 U50.A14 U50.A15 U50.A16 U50.B2 U50.B3 U50.B4 U50.B5 U50.B6 U50.B7 U50.B8 U50.B9 U50.B10 U50.B11 U50.B12 U50.B13 U50.B14 U50.B15 U50.C3 U50.C10 U50.C15 U50.C16 U50.D13 U50.D15 U50.D16 U50.E2 U50.E15 U50.E16 U50.F1 U50.F2 U50.F3 U50.F14 U50.F16 U50.G1 U50.G2 U50.G3 U50.G4 U50.G13 U50.G14 U50.G16 U50.H1 U50.H2 U50.H3 U50.H4 U50.H14 U50.J1 U50.J2 U50.J3 U50.J4 U50.J14 U50.J15 U50.J16 U50.K1 U50.K2 U50.K3 U50.K4 U50.K13 U50.K14 U50.K15 U50.K16 U50.L1 U50.L2 U50.L4 U50.L13 U50.L14 U50.L15 U50.L16 U50.M1 U50.M2 U50.N1 U50.N3 U50.N4 U50.P1 U50.P4 U50.R2 U50.R3 U50.R4 U50.R5 U50.R6 U50.R7 U50.R8 U50.R9 U50.R12 U50.R13 U50.T1 U50.T2 U50.T3 U50.T4 U50.T5 U50.T6 U50.T7 U50.T8 U50.T9 U50.T12 U50.T13 U50.T16 U63.1 U63.2 U63.3 U63.7 USB1. USB1.4 USBC1. USBC1.A8 USBC1.B8 Y3.2

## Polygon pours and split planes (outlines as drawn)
GND on Top Layer 1 _Signal "NONET_L04_P-001" (solid, pour order 365): 190.092,137.345 293.819,137.81 294.746,137.471 294.513,-0.149 191.373,0 189.339,3.107
GND on Top Layer 1 _Signal "NONET_L04_P-001" (solid, pour order 355): 147.761,86.461 165.701,86.461 165.701,74.348 161.051,69.698 145.993,69.698 145.993,84.57
GND on Top Layer 1 _Signal "NONET_L04_P-001" (solid, pour order 362): 0.053,138.123 123.253,138.541 123.253,2.141 121.357,0.245 0.053,0.245
RP_1V1 on Top Layer 1 _Signal "NONET_L04_P-001" (solid, pour order 209): 11.233,118.925 11.25,118.942 13.405,118.942 13.581,119.119 15.413,119.119 15.569,118.962 15.569,117.883 16.353,117.099 19.451,117.099 19.451,116.769 19.386,116.704 15.569,116.704 14.581,117.692 11.219,117.692
3V3 on Top Layer 1 _Signal "NONET_L04_P-001" (solid, pour order 243): 58.488,112.03 58.522,112.065 60.346,112.065 61.221,112.94 61.221,113.913 62.1,113.913 62.194,113.819 62.194,111.971 61.828,111.605 58.468,111.605
3V3 on Top Layer 1 _Signal "NONET_L04_P-001" (solid, pour order 215): 59.382,121.796 59.44,121.854 62.664,121.854 62.664,121.48 62.651,121.468 62.639,121.48 59.374,121.48
NetC313_1 on Top Layer 1 _Signal "NONET_L04_P-001" (solid, pour order 248): 275.827,33.82 275.827,32.628 276.065,32.39 276.065,31.849 275.454,31.849 275.276,31.671 274.159,31.671 274.159,32.378 274.354,32.573 275.165,32.573 275.165,33.614 275.385,33.833
5V on Top Layer 1 _Signal "NONET_L04_P-001" (solid, pour order 144): 247.278,92.475 248.203,92.475 248.203,91.017 248.616,90.604 248.616,85.494 247.598,85.494 246.796,86.296 246.796,91.33 247.251,91.784 247.251,92.451
NetR184_2 on Top Layer 1 _Signal "NONET_L04_P-001" (solid, pour order 139): 232.626,86.004 232.626,87.703 232.813,87.891 234.024,87.891 234.024,89.238 234.327,89.541 236.312,89.541 236.568,89.285 237.234,89.285 237.234,88.73 237.151,88.647 235.105,88.647 235.105,86.849 233.008,86.849 233.008,85.989
5V on Top Layer 1 _Signal "NONET_L04_P-001" (solid, pour order 152): 241.357,72.927 240.478,73.806 240.478,77.69 239.562,78.605 237.92,78.605 237.92,73.24 239.658,73.24 240.383,72.516 240.383,71.701 241.249,71.701 241.277,71.729
NetL28_1 on Top Layer 1 _Signal "NONET_L04_P-001" (solid, pour order 170): 225.165,103.967 229.096,103.967 229.923,104.794 229.923,110.824 226.511,110.824 226.511,104.713 226.194,104.396 225.165,104.396
NetR269_1 on Top Layer 1 _Signal "NONET_L04_P-001" (solid, pour order 171): 224.459,103.94 223.316,103.94 223.26,103.884 221.429,103.884 221.429,104.434 221.648,104.653 223.351,104.653 223.552,104.452 224.454,104.452
NetC313_1 on Top Layer 1 _Signal "NONET_L04_P-001" (solid, pour order 241): 281.053,33.784 281.053,31.913 281.146,31.82 281.151,31.825 282.428,31.825 282.511,31.908 282.497,31.923 282.497,33.779
PMIC_SW7 on Top Layer 1 _Signal "NONET_L04_P-001" (solid, pour order 77): 91.169,57.44 91.169,57.619 91.184,57.634 91.142,57.676 87.605,57.676 80.987,51.059 73.403,51.059 73.027,50.682 73.027,49.106 78.535,49.106 78.561,49.132 80.313,49.132 88.553,57.372 91.17,57.372
VOUT7 on Top Layer 1 _Signal "NONET_L04_P-001" (solid, pour order 76): 91.134,57.981 91.096,57.944 85.974,57.944 82.686,54.656 67.355,54.656 67.355,52.372 82.096,52.372 87.412,57.688 91.192,57.688
PMIC_EXT_EN_OUT on Top Layer 1 _Signal "NONET_L04_P-001" (solid, pour order 74): 91.118,58.69 90.011,58.69 89.801,58.9 87.074,58.9 87.074,58.408 91.118,58.408
5V on Top Layer 1 _Signal "NONET_L04_P-001" (solid, pour order 246): 239.768,104.19 239.775,104.197 240.809,104.197 241.131,103.875 241.131,96.86 239.507,96.86 239.507,104.176
VDD_NPU_S0 on Top Layer 1 _Signal "NONET_L04_P-001" (solid, pour order 325): 185.673,20.265 185.666,20.258 185.666,18.55 179.558,18.55 175.593,22.515 175.593,26.314 178.268,26.314 178.304,26.35 178.304,23.343 181.741,19.906 184.787,19.906 185.186,20.305
1V2 on Top Layer 1 _Signal "NONET_L04_P-001" (solid, pour order 363): 250.967,94.382 253.93,94.382 255.146,93.166 255.146,92.081 255.131,92.096 255.093,92.058 252.276,92.058 252.276,86.739 251.683,86.147 250.698,86.147 250.698,94.382 250.808,94.382
1V8 on Top Layer 1 _Signal "NONET_L04_P-001" (solid, pour order 137): 26 vertices, not listed, extent 230.18,85.866 240.944,94.577
1V8_DP on Top Layer 1 _Signal "NONET_L04_P-001" (solid, pour order 149): 242.154,71.808 243.042,71.808 243.042,72.399 243.246,72.603 244.1,72.603 244.1,78.595 243.781,78.913 242.235,78.913 242.235,84.848 245.282,84.848 245.282,70.549 244.137,70.549 243.294,71.392 242.142,71.392
NetC602_2 on Top Layer 1 _Signal "NONET_L04_P-001" (solid, pour order 150): 236.038,71.555 241.268,71.555 241.534,71.289 241.534,69.368 240.992,68.826 240.992,68.17 240.215,68.17 240.215,68.673 241.055,69.513 241.055,70.653 236.05,70.653
VOUT6 on Top Layer 1 _Signal "NONET_L04_P-001" (solid, pour order 360): 123.176,85.203 124.178,85.171 125.622,85.171 125.622,83.426 125.434,83.238 124.183,83.238 123.176,83.292 123.137,83.292
VDD_LOG_S0 on Top Layer 1 _Signal "NONET_L04_P-001" (solid, pour order 24): 92.995,54.076 92.995,50.89 88.469,50.89 88.469,45.905 88.123,45.559 88.113,45.569 86.508,45.569 86.508,49.814 88.408,51.713 92.697,51.713 92.697,54.076
NLDO2 on Top Layer 1 _Signal "NONET_L04_P-001" (solid, pour order 318): 30 vertices, not listed, extent 100.351,62.92 112.305,71.055
VCC_2V0_PLDO_S3 on Top Layer 1 _Signal "NONET_L04_P-001" (solid, pour order 28): 93.985,54.052 93.985,48.476 91.974,48.444 91.974,46.864 91.974,45.784 91.218,45.784 91.175,45.827 91.175,49.072 91.278,49.175 93.458,49.175 93.722,49.439 93.722,54.041 93.738,54.057
VCC1 on Top Layer 1 _Signal "NONET_L04_P-001" (solid, pour order 71): 91.903,60.421 91.903,61.049 91.013,61.938 84.641,61.938 82.82,63.759 80.581,63.759 79.859,64.481 74.695,64.481 74.695,63.143 82.358,63.143 85.08,60.421
0V9 on Top Layer 1 _Signal "NONET_L04_P-001" (solid, pour order 135): 287.149,55.054 287.149,56.38 287.663,56.895 289.287,56.895 289.287,65.632 287.571,65.632 287.571,58.492 287.274,58.195 273.606,58.195 273.606,55.879 286.832,55.879 286.832,55.107
VCC1 on Top Layer 1 _Signal "NONET_L04_P-001" (solid, pour order 123): 191.903,29.165 189.431,29.165 189.431,28.115 190.905,28.115 191.303,28.513 191.897,28.513
VDD_CPU_BIG1_S0 on Top Layer 1 _Signal "NONET_L04_P-001" (solid, pour order 126): 209.236,32.521 209.321,32.521 212.294,32.521 212.294,29.519 212.173,29.398 210.702,29.398 210.666,29.433 210.666,31.856 210.671,31.861 210.626,31.907 209.236,31.907
EMMC_VCC on Top Layer 1 _Signal "NONET_L04_P-001" (solid, pour order 130): 199.628,19.142 196.684,19.142 196.39,19.436 196.39,20.326 199.418,20.326 199.586,20.159
VCC14 on Top Layer 1 _Signal "NONET_L04_P-001" (solid, pour order 131): 206.775,27.148 206.775,22.464 212.067,22.464 212.361,22.758 212.361,27.177
2V5_DP on Top Layer 1 _Signal "NONET_L04_P-001" (solid, pour order 196): 242.492,33.801 242.579,33.713 242.579,30.394 241.549,30.394 240.64,31.303 240.64,33.316 239.853,34.104 238.54,34.104 238.54,34.44 238.594,34.494 241.085,34.494 241.759,33.821 242.33,33.821
1V8_DP on Top Layer 1 _Signal "NONET_L04_P-001" (solid, pour order 198): 236.768,30.692 236.757,30.681 236.757,30.51 237.488,30.51 237.911,30.087 240.126,30.087 240.126,31.06 238.979,31.06 238.979,33.094 238.208,33.094 238.208,32.363 236.762,30.917
VDD_CPU_BIG0_S0 on Top Layer 1 _Signal "NONET_L04_P-001" (solid, pour order 328): 180.263,16.206 180.263,14.429 179.95,14.115 179.95,12.223 178.831,11.104 176.357,11.104 176.357,16.242
NetC51_1 on Top Layer 1 _Signal "NONET_L04_P-001" (solid, pour order 93): 78.459,41.723 78.442,41.706 75.856,41.706 74.935,40.784 70.309,40.784 70.309,38.728 70.489,38.548 75.182,38.548 76.496,39.862 78.442,39.862
12V on Top Layer 1 _Signal "NONET_L04_P-001" (solid, pour order 134): 286.835,53.328 286.797,53.29 285.321,53.29 285.321,52.094 285.2,51.973 276.631,51.973 276.631,54.183 276.67,54.222 286.827,54.222
1V1 on Top Layer 1 _Signal "NONET_L04_P-001" (solid, pour order 340): 17 vertices, not listed, extent 234.068,54.836 239.212,58.152
PWRON_L on Top Layer 1 _Signal "NONET_L04_P-001" (solid, pour order 38): 97.322,55.215 107.274,55.215 107.274,54.376 109.234,54.376 109.234,56.079 106.704,56.079 106.22,55.596 97.322,55.596
VCC1 on Top Layer 1 _Signal "NONET_L04_P-001" (solid, pour order 194): 58.84,58.526 cw(c58.84,55.316) 61.638,56.89 61.638,53.819 58.742,53.819 cw(c58.742,55.836) 57.315,54.41 cw(c57.471,54.565) 57.251,54.565 57.251,68.499 cw(c59.369,68.499) 57.871,69.997 59.017,69.997
12V on Top Layer 1 _Signal "NONET_L04_P-001" (solid, pour order 342): 11.075,89.883 10.879,89.687 6.651,89.687 6.651,75.897 11.392,71.156 22.722,71.156 22.722,73.596 21.621,74.697 12.218,74.697 9.464,77.451 9.464,87.326 10.723,87.326 11.057,87.661
12V on Top Layer 1 _Signal "NONET_L04_P-001" (solid, pour order 238): 29.112,84.464 30.203,84.464 30.242,84.425 30.48,84.663 31.393,84.663 31.413,84.682 31.438,84.657 31.438,82.894 31.628,82.704 31.628,72.887 26.185,72.887 26.185,84.556
NetQ14_2 on Top Layer 1 _Signal "NONET_L04_P-001" (solid, pour order 219): 25.967,25.64 26.028,25.578 26.028,20.455 25.384,19.811 8.143,19.811 4.186,23.768 4.186,50.059 4.584,50.458 11.732,50.458 11.732,26.069 16.089,21.713 24.157,21.713 24.74,22.296 24.74,25.64
+24V on Top Layer 1 _Signal "NONET_L04_P-001" (solid, pour order 341): 18.705,37.819 18.778,37.746 20.457,37.746 20.457,37.221 23.333,34.345 23.464,34.345 23.464,32.973 23.406,32.914 19.493,32.914 19.493,33.119 17.873,34.739 17.873,36.944
+24V on Top Layer 1 _Signal "NONET_L04_P-001" (solid, pour order 228): 38.609,54.647 38.609,59.645 39.031,60.067 40.797,60.067 41.286,59.578 41.286,58.09 41.741,57.635 43.018,57.635 43.018,54.796 42.869,54.647 39.886,54.647
+24V on Top Layer 1 _Signal "NONET_L04_P-001" (solid, pour order 225): 3.57,59.395 11.945,59.395 16.051,55.29 21.339,55.29 21.339,46.914 20.814,46.389 3.471,46.389
1V1 on Top Layer 1 _Signal "NONET_L04_P-001" (solid, pour order 197): 242.458,34.467 242.458,36.648 242.195,36.911 242.195,37.786 241.691,37.786 241.388,37.483 241.388,36.224 241.199,36.036 238.573,36.036 238.573,35.601 240.254,35.601 241.421,34.434 242.047,34.434
1V8 on Top Layer 1 _Signal "NONET_L04_P-001" (solid, pour order 182): 275.268,37.523 275.232,37.56 272.745,37.56 272.03,36.846 272.03,36.545 271.418,36.545 271.418,37.469 272.047,37.469 272.268,37.689 272.268,38.206 273.391,38.206 273.727,37.871 275.183,37.871 275.256,37.798
1V8_DP on Top Layer 1 _Signal "NONET_L04_P-001" (solid, pour order 206): 233.853,52.133 233.841,52.121 233.841,50.489 232.523,50.489 232.294,50.26 232.294,49.432 235.44,49.432 235.71,49.702 235.878,49.702 235.878,50.335 234.073,52.141
2V5_DP on Top Layer 1 _Signal "NONET_L04_P-001" (solid, pour order 207): 234.126,53.695 236.066,53.695 236.108,55.225 237.201,55.249 237.201,50.521 236.76,50.521 236.596,50.685 236.596,52.817 236.184,53.229 234.178,53.229
2V5_DP on Top Layer 1 _Signal "NONET_L04_P-001" (solid, pour order 174): 249.046,100.097 249.046,114.51 248.257,115.298 240.196,115.298 240.196,114.081 240.591,113.686 245.273,113.686 245.273,100.097
VDD_VDENC_S0 on Top Layer 1 _Signal "NONET_L04_P-001" (solid, pour order 60): 94.992,60.308 94.992,63.686 93.799,64.879 93.799,71.969 95.224,71.969 95.224,74.091 90.525,74.091 90.499,74.117 90.447,74.065 90.447,70.271 93.268,70.271 93.268,64.496 94.722,63.042 94.722,60.378
VDD_VDENC_S0 on Top Layer 1 _Signal "NONET_L04_P-001" (solid, pour order 62): 95.034,71.937 95.212,72.115 95.212,74.506 97.292,74.506 97.373,74.587 97.373,75.731 96.152,75.731 96.146,75.738 95.612,75.204 93.546,75.204 93.546,72.185 93.743,71.988
NLDO4 on Top Layer 1 _Signal "NONET_L04_P-001" (solid, pour order 333): 17 vertices, not listed, extent 102.536,60.092 128.288,68.39
VOUT9 on Top Layer 1 _Signal "NONET_L04_P-001" (solid, pour order 336): 30 vertices, not listed, extent 100.362,45.287 141.321,69.363
EMMC_VCC on Top Layer 1 _Signal "NONET_L04_P-001" (solid, pour order 40): 97.281,55.963 103.796,55.963 105.259,57.426 111.119,57.426 111.119,55.037 110.859,54.777 109.697,54.777 109.299,55.175 109.299,56.167 106.673,56.167 106.08,55.573 97.302,55.573
NLDO3 on Top Layer 1 _Signal "NONET_L04_P-001" (solid, pour order 330): 21 vertices, not listed, extent 101.691,60.981 133.47,70.118
NetC502_1 on Top Layer 1 _Signal "NONET_L04_P-001" (solid, pour order 327): 22 vertices, not listed, extent 180.078,6.601 200.831,16.2
VDD_NPU_S0 on Top Layer 1 _Signal "NONET_L04_P-001" (solid, pour order 324): 178.46,26.347 177.316,26.347 177.251,26.283 175.199,28.335 173.897,28.335 172.875,27.313 176.064,24.123 178.424,24.123
VDD_CPU_BIG1_S0 on Top Layer 1 _Signal "NONET_L04_P-001" (solid, pour order 322): 197.313,40.783 196.881,41.214 189.506,41.214 189.506,39.079 189.519,39.092 197.324,39.092
NetC494_1 on Top Layer 1 _Signal "NONET_L04_P-001" (solid, pour order 125): 196.187,38.459 196.217,38.489 201.906,38.489 204.323,36.072 211.205,36.072 212.232,35.045 212.232,32.828 205.103,32.828 202.757,35.175 196.187,35.175
NetC511_1 on Top Layer 1 _Signal "NONET_L04_P-001" (solid, pour order 290): 176.22,29.437 187.745,29.288 187.745,18.942 188.154,18.534 185.918,18.534 185.918,22.95 184.983,23.885 184.983,27.482 176.22,27.482
EMMC_VCC on Top Layer 1 _Signal "NONET_L04_P-001" (solid, pour order 319): 111.071,62.069 111.081,62.06 112.43,62.06 112.43,61.151 112.647,60.934 117.251,60.934 117.251,59.031 116.97,58.749 111.015,58.749
PMIC_SW8 on Top Layer 1 _Signal "NONET_L04_P-001" (solid, pour order 41): 97.387,55.98 97.4,55.967 103.523,55.967 105.102,57.546 108.837,57.546 108.837,62.298 108.614,62.522 107.14,62.522 107.14,58.643 104.867,58.643 102.515,56.292 97.382,56.292
EMMC_VCC on Top Layer 1 _Signal "NONET_L04_P-001" (solid, pour order 314): 112.226,62.189 112.404,62.01 112.404,58.361 111.755,58.361 110.717,57.323 110.814,57.226 110.814,54.922 109.857,54.922 109.436,55.344 109.436,57.754 110.312,58.831 110.814,59.334 110.814,62.189
VCC1 on Top Layer 1 _Signal "NONET_L04_P-001" (solid, pour order 58): 96.029,60.295 96.029,63.521 95.504,63.521 95.504,60.295
VCC1 on Top Layer 1 _Signal "NONET_L04_P-001" (solid, pour order 66): 93.973,60.326 93.973,61.638 93.872,61.739 92.401,63.21 92.329,63.139 92.329,62.55 93.383,61.496 93.383,60.29
PLDO4 on Top Layer 1 _Signal "NONET_L04_P-001" (solid, pour order 31): 94.966,53.999 94.966,48.222 94.966,45.982 95.293,45.655 95.324,45.687 96.272,45.687 96.272,48.512 96.272,50.195 95.372,51.095 95.372,53.999
VCC1 on Top Layer 1 _Signal "NONET_L04_P-001" (solid, pour order 92): 92.245,54.181 92.23,54.166 92.23,52.627 88.974,52.644 88.974,53.415 91.384,53.415 91.384,54.2
VCC1 on Top Layer 1 _Signal "NONET_L04_P-001" (solid, pour order 310): 105.131,54.992 105.16,54.964 105.763,54.964 105.763,53.78 107.098,52.445 107.098,46.757 106.095,46.757 105.369,47.483 105.369,52.973 104.01,54.332 104.01,54.979
VCC1 on Top Layer 1 _Signal "NONET_L04_P-001" (solid, pour order 39): 97.481,54.476 97.489,54.484 99.748,54.484 100.325,55.061 105.665,55.061 105.763,54.964 105.763,53.753 104.202,53.753 103.755,54.2 97.497,54.2
NLDO5 on Top Layer 1 _Signal "NONET_L04_P-001" (solid, pour order 43): 97.532,56.751 99.561,56.751 99.997,57.187 104.166,57.187 104.166,59.333 102.297,59.333 99.873,56.909 97.446,56.909
PLDO5 on Top Layer 1 _Signal "NONET_L04_P-001" (solid, pour order 33): 95.868,53.856 95.857,53.846 95.857,52.947 95.857,51.728 96.467,51.118 96.467,45.898 96.638,45.727 97.312,45.727 97.312,50.936 96.039,52.209 96.039,53.846
PLDO4 on Top Layer 1 _Signal "NONET_L04_P-001" (solid, pour order 231): 38.135,77.755 38.11,77.731 36.656,77.731 35.835,76.909 35.835,75.857 36.122,75.57 36.31,75.57 36.423,75.456 36.423,74.76 36.581,74.602 38.141,74.602
VDD_DDR_S0 on Top Layer 1 _Signal "NONET_L04_P-001" (solid, pour order 81): 91.188,56.216 88.489,56.216 79.596,47.12 78.359,45.883 78.359,44.397 78.371,44.385 78.088,44.102 68.642,44.102 68.642,41.926 78.901,41.926 78.901,45.174 89.317,55.89 91.17,55.89
VOUT6 on Top Layer 1 _Signal "NONET_L04_P-001" (solid, pour order 96): 80.843,80.909 80.843,71.451 80.625,71.234 79.094,71.234 79.094,73.609 79.912,74.427 79.912,80.674 80.138,80.901
VCCA_1V8 on Top Layer 1 _Signal "NONET_L04_P-001" (solid, pour order 29): 94.305,54.027 94.305,48.194 94.115,48.004 93.455,48.004 93.455,46.06 93.295,45.901 93.288,45.908 92.505,45.908 92.505,48.24 92.643,48.378 93.98,48.378 94.093,48.491 94.093,54.08
VDD_CPU_LIT_S0 on Top Layer 1 _Signal "NONET_L04_P-001" (solid, pour order 73): 91.243,59.125 91.243,59.422 85.709,59.403 84.809,58.503 78.286,58.503 77.628,59.161 75.841,59.161 75.841,55.354 76.225,54.97 77.994,54.97 78.286,54.97 78.286,57.366 85.359,57.366 86.933,58.939 91.243,58.939
NLDO2 on Top Layer 1 _Signal "NONET_L04_P-001" (solid, pour order 51): 101.047,63.484 101.047,60.729 98.383,58.065 97.264,58.065 97.264,58.3 97.255,58.308 98.169,58.308 100.39,60.53 100.39,63.512
5V on Top Layer 1 _Signal "NONET_L04_P-001" (solid, pour order 136): 232.277,84.147 232.259,84.129 225.24,84.129 225.218,84.151 225.218,85.076 231.894,85.076 232.282,84.688
VOUT9 on Top Layer 1 _Signal "NONET_L04_P-001" (solid, pour order 36): 96.541,53.986 96.534,53.979 96.534,52.603 98.385,50.752 98.385,48.447 100.448,46.384 100.448,45.609 100.619,45.609 100.814,45.609 104.618,45.609 104.618,48.016 104.618,51.226 98.76,51.226 96.819,53.167 96.819,54.074
1V1 on Top Layer 1 _Signal "NONET_L04_P-001" (solid, pour order 249): 24 vertices, not listed, extent 269.017,34.759 275.28,40.542
NetC372_1 on Top Layer 1 _Signal "NONET_L04_P-001" (solid, pour order 247): 275.243,34.923 273.913,34.923 273.606,35.231 273.606,35.985 272.815,35.985 272.753,35.975 272.702,35.975 272.702,33.308 272.804,33.206 273.514,33.206 273.653,33.345 273.653,34.429 275.26,34.429
3V3 on Top Layer 1 _Signal "NONET_L04_P-001" (solid, pour order 244): 58.285,112.762 58.285,115.366 59.298,116.379 60.85,116.379 61.207,116.022 61.207,113.503 62.14,113.503 62.209,113.572 62.199,113.582 62.199,116.824 61.888,117.135 57.924,117.135 57.475,116.686 57.475,112.787
3V3 on Top Layer 1 _Signal "NONET_L04_P-001" (solid, pour order 201): 45.212,114.198 45.152,114.258 43.712,114.258 43.712,112.498 44.254,112.498 44.47,112.714 44.47,113.681 44.695,113.905 45.25,113.905
2V5_VSC on Top Layer 1 _Signal "NONET_L04_P-001" (solid, pour order 169): 226.571,114.435 234.692,114.435 235.068,114.059 235.068,104.551 231.591,104.551 231.591,112.788 231.134,113.246 226.535,113.246
3V3 on Top Layer 1 _Signal "NONET_L04_P-001" (solid, pour order 245): 54.796,112.663 54.796,114.993 54.362,115.427 52.124,115.427 52.124,114.249 52.358,114.015 53.536,114.015 54.014,113.537 54.014,112.709
NetC670_2 on Top Layer 1 _Signal "NONET_L04_P-001" (solid, pour order 242): 238.763,104.159 238.67,104.066 238.67,99.09 237.784,99.09 237.784,99.176 237.784,99.276 237.784,103.795 238.149,104.159
12V on Top Layer 1 _Signal "NONET_L04_P-001" (solid, pour order 232): 38.94,78.425 38.94,76.904 38.983,76.904 39.734,76.153 39.734,72.603 28.27,72.603 24.001,68.335 24.001,66.907 17.1,66.907 16.713,67.295 16.713,70.473 20.575,74.334 38.303,74.334 38.439,74.471 38.439,78.437
5V on Top Layer 1 _Signal "NONET_L04_P-001" (solid, pour order 237): 20 vertices, not listed, extent 31.589,86.901 39.549,99.859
